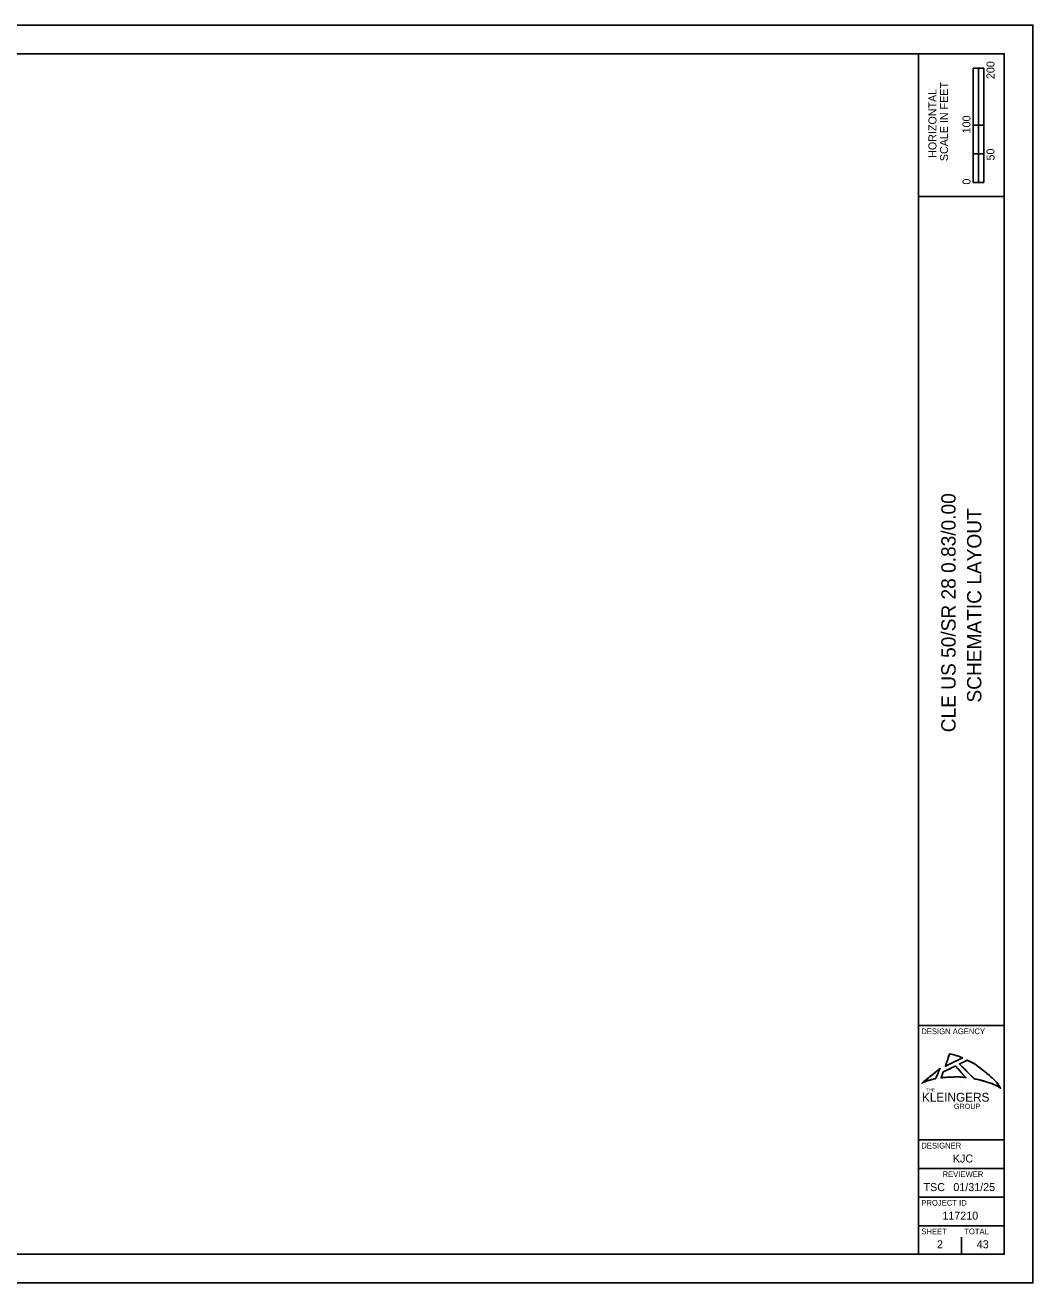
# Model space of a CAD drawing. Extents: x -1.2 to 34, y 0 to 22.
# Drawn here: x 16.38 to 34, y 0 to 22 of the extents above; entities that cross this region are included whole.
import ezdxf

# ---------------------------------------------------------------- set-up
doc = ezdxf.new("R2010")
doc.units = 0
for name, color, linetype in [('SH_Border', 7, 'Continuous'), ('SH_Cut_Line', 7, 'Continuous'), ('SH_Data', 7, 'Continuous'), ('SH_Text', 7, 'Continuous')]:
    doc.layers.add(name, color=color, linetype=linetype)

msp = doc.modelspace()

# ---------------------------------------------------------------- linework, layer by layer
at = {"layer": 'SH_Border'}
for p, q in [((32, 0.5), (32, 21.5)), ((32, 19), (33.5, 19)), ((32, 4.5), (33.5, 4.5)), ((32, 2.5), (33.5, 2.5)), ((32, 2), (33.5, 2)), ((32, 1.5), (33.5, 1.5)), ((32, 1), (33.5, 1))]:
    msp.add_line(p, q, dxfattribs=at)
msp.add_lwpolyline([(1.5, 21.5), (33.5, 21.5), (33.5, 0.5), (1.5, 0.5)], close=True, dxfattribs=at)
at = {"layer": 'SH_Cut_Line'}
msp.add_lwpolyline([(0, 0), (34, 0), (34, 22), (0, 22)], close=True, dxfattribs=at)
at = {"layer": 'SH_Data'}
for p, q in [((32.957, 19.25), (32.957, 21.25)), ((33.144, 21.25), (32.957, 21.25)), ((32.957, 20.25), (32.957, 21.25)), ((32.957, 21.25), (33.05, 21.25)), ((33.05, 21.25), (33.051, 21.25)), ((33.051, 21.25), (33.051, 20.25)), ((33.144, 21.25), (33.144, 19.25)), ((33.051, 20.25), (32.957, 20.25)), ((33.143, 20.25), (33.05, 20.25)), ((33.05, 20.25), (33.05, 19.75)), ((33.143, 19.75), (33.143, 20.25)), ((33.05, 19.75), (32.957, 19.75)), ((32.957, 19.75), (32.957, 19.25)), ((33.05, 19.25), (33.05, 19.75)), ((33.05, 19.75), (33.143, 19.75)), ((33.144, 19.25), (32.957, 19.25)), ((32.957, 19.25), (33.05, 19.25)), ((32.75, 3.5), (32.75, 3.5)), ((32.375, 0.675), (32.375, 0.675)), ((32.75, 0.5), (32.75, 0.8))]:
    msp.add_line(p, q, dxfattribs=at)
at = {"layer": 'SH_Text'}
for points, degree in [([(32.542, 4.004), (32.542, 4.004), (32.47, 3.788), (32.47, 3.788)], 2), ([(32.772, 3.935), (32.772, 3.935), (32.722, 3.958), (32.655, 3.979), (32.588, 3.999), (32.542, 4.004), (32.542, 4.004), (32.542, 4.004), (32.47, 3.788), (32.47, 3.788), (32.47, 3.788), (32.772, 3.935), (32.772, 3.935)], 3), ([(32.772, 3.935), (32.772, 3.935), (32.722, 3.958), (32.655, 3.979)], 2), ([(32.379, 3.752), (32.379, 3.752), (32.061, 3.492), (32.061, 3.492)], 2), ([(32.379, 3.752), (32.379, 3.752), (32.061, 3.492), (32.061, 3.492), (32.061, 3.492), (32.133, 3.529), (32.21, 3.55), (32.28, 3.569), (32.303, 3.572), (32.303, 3.572), (32.303, 3.572), (32.379, 3.752), (32.379, 3.752)], 3), ([(32.303, 3.572), (32.303, 3.572), (32.379, 3.752), (32.379, 3.752)], 2), ([(32.648, 3.793), (32.648, 3.793), (32.83, 3.589), (32.83, 3.589), (32.83, 3.589), (32.734, 3.604), (32.602, 3.6), (32.455, 3.595), (32.396, 3.584), (32.396, 3.584), (32.396, 3.584), (32.434, 3.691), (32.434, 3.691), (32.434, 3.691), (32.648, 3.793), (32.648, 3.793)], 3), ([(32.434, 3.691), (32.434, 3.691), (32.648, 3.793), (32.648, 3.793)], 2), ([(32.47, 3.788), (32.47, 3.788), (32.772, 3.935), (32.772, 3.935)], 2), ([(32.648, 3.793), (32.648, 3.793), (32.83, 3.589), (32.83, 3.589)], 2), ([(33.2, 3.512), (33.079, 3.551), (32.978, 3.567), (32.978, 3.567), (32.978, 3.567), (32.717, 3.827), (32.717, 3.827), (32.717, 3.827), (32.855, 3.894), (32.855, 3.894), (32.855, 3.894), (32.985, 3.834), (33.142, 3.708), (33.348, 3.542), (33.438, 3.405), (33.438, 3.405), (33.438, 3.405), (33.351, 3.463), (33.2, 3.512)], 3), ([(32.717, 3.827), (32.717, 3.827), (32.855, 3.894), (32.855, 3.894)], 2), ([(32.978, 3.567), (32.978, 3.567), (32.717, 3.827), (32.717, 3.827)], 2), ([(32.855, 3.894), (32.855, 3.894), (32.985, 3.834), (33.142, 3.708)], 2), ([(32.061, 3.492), (32.061, 3.492), (32.133, 3.529), (32.21, 3.55)], 2), ([(32.21, 3.55), (32.28, 3.569), (32.303, 3.572), (32.303, 3.572)], 2), ([(32.396, 3.584), (32.396, 3.584), (32.434, 3.691), (32.434, 3.691)], 2), ([(32.602, 3.6), (32.455, 3.595), (32.396, 3.584), (32.396, 3.584)], 2), ([(32.83, 3.589), (32.83, 3.589), (32.734, 3.604), (32.602, 3.6)], 2), ([(33.2, 3.512), (33.079, 3.551), (32.978, 3.567), (32.978, 3.567)], 2), ([(33.142, 3.708), (33.348, 3.542), (33.438, 3.405), (33.438, 3.405)], 2), ([(33.438, 3.405), (33.438, 3.405), (33.351, 3.463), (33.2, 3.512)], 2)]:
    msp.add_open_spline(points, degree=degree, dxfattribs=at)

# ---------------------------------------------------------------- texts
at = {"layer": 'SH_Data'}
for s, height, p in [('200', 0.14, (33.33, 21.057)), ('SCALE IN FEET', 0.14, (32.517, 19.621)), ('HORIZONTAL', 0.14, (32.315, 19.679)), ('100', 0.14, (32.91, 20.107)), ('50', 0.14, (33.33, 19.633)), ('0', 0.14, (32.91, 19.211)), ('CLE US 50/SR 28 0.83/0.00', 0.25, (32.65, 9.631)), ('SCHEMATIC LAYOUT', 0.25, (33.1, 10.15))]:
    msp.add_text(s, height=height, rotation=90, dxfattribs=at).set_placement(p)
for s, height, p in [('DESIGN AGENCY', 0.1, (32.05, 4.35)), ('DESIGNER', 0.1, (32.05, 2.35)), ('KJC', 0.14, (32.602, 2.105)), ('REVIEWER', 0.1, (32.422, 1.85)), ('TSC', 0.14, (32.09, 1.605)), ('01/31/25', 0.14, (32.611, 1.605)), ('PROJECT ID', 0.1, (32.05, 1.35)), ('117210', 0.14, (32.419, 1.105)), ('SHEET', 0.1, (32.05, 0.85)), ('TOTAL', 0.1, (32.8, 0.85)), ('2', 0.14, (32.325, 0.605)), ('43', 0.14, (33.02, 0.605))]:
    msp.add_text(s, height=height, dxfattribs=at).set_placement(p)
at = {"layer": 'SH_Text'}
for s, height, p in [('KLEINGERS', 0.1542, (32.061, 3.17)), ('THE', 0.0561, (32.135, 3.349)), ('GROUP', 0.0911, (32.62, 3.042))]:
    msp.add_text(s, height=height, dxfattribs=at).set_placement(p)

doc.saveas('drawing.dxf')
